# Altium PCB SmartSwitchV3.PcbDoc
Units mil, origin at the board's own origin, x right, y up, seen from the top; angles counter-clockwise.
Board outline 3850.26 x 3794.87 mil, 2 copper layers (Top Layer, Bottom Layer); 87 components, 65 nets, 326 pads, 45 vias.
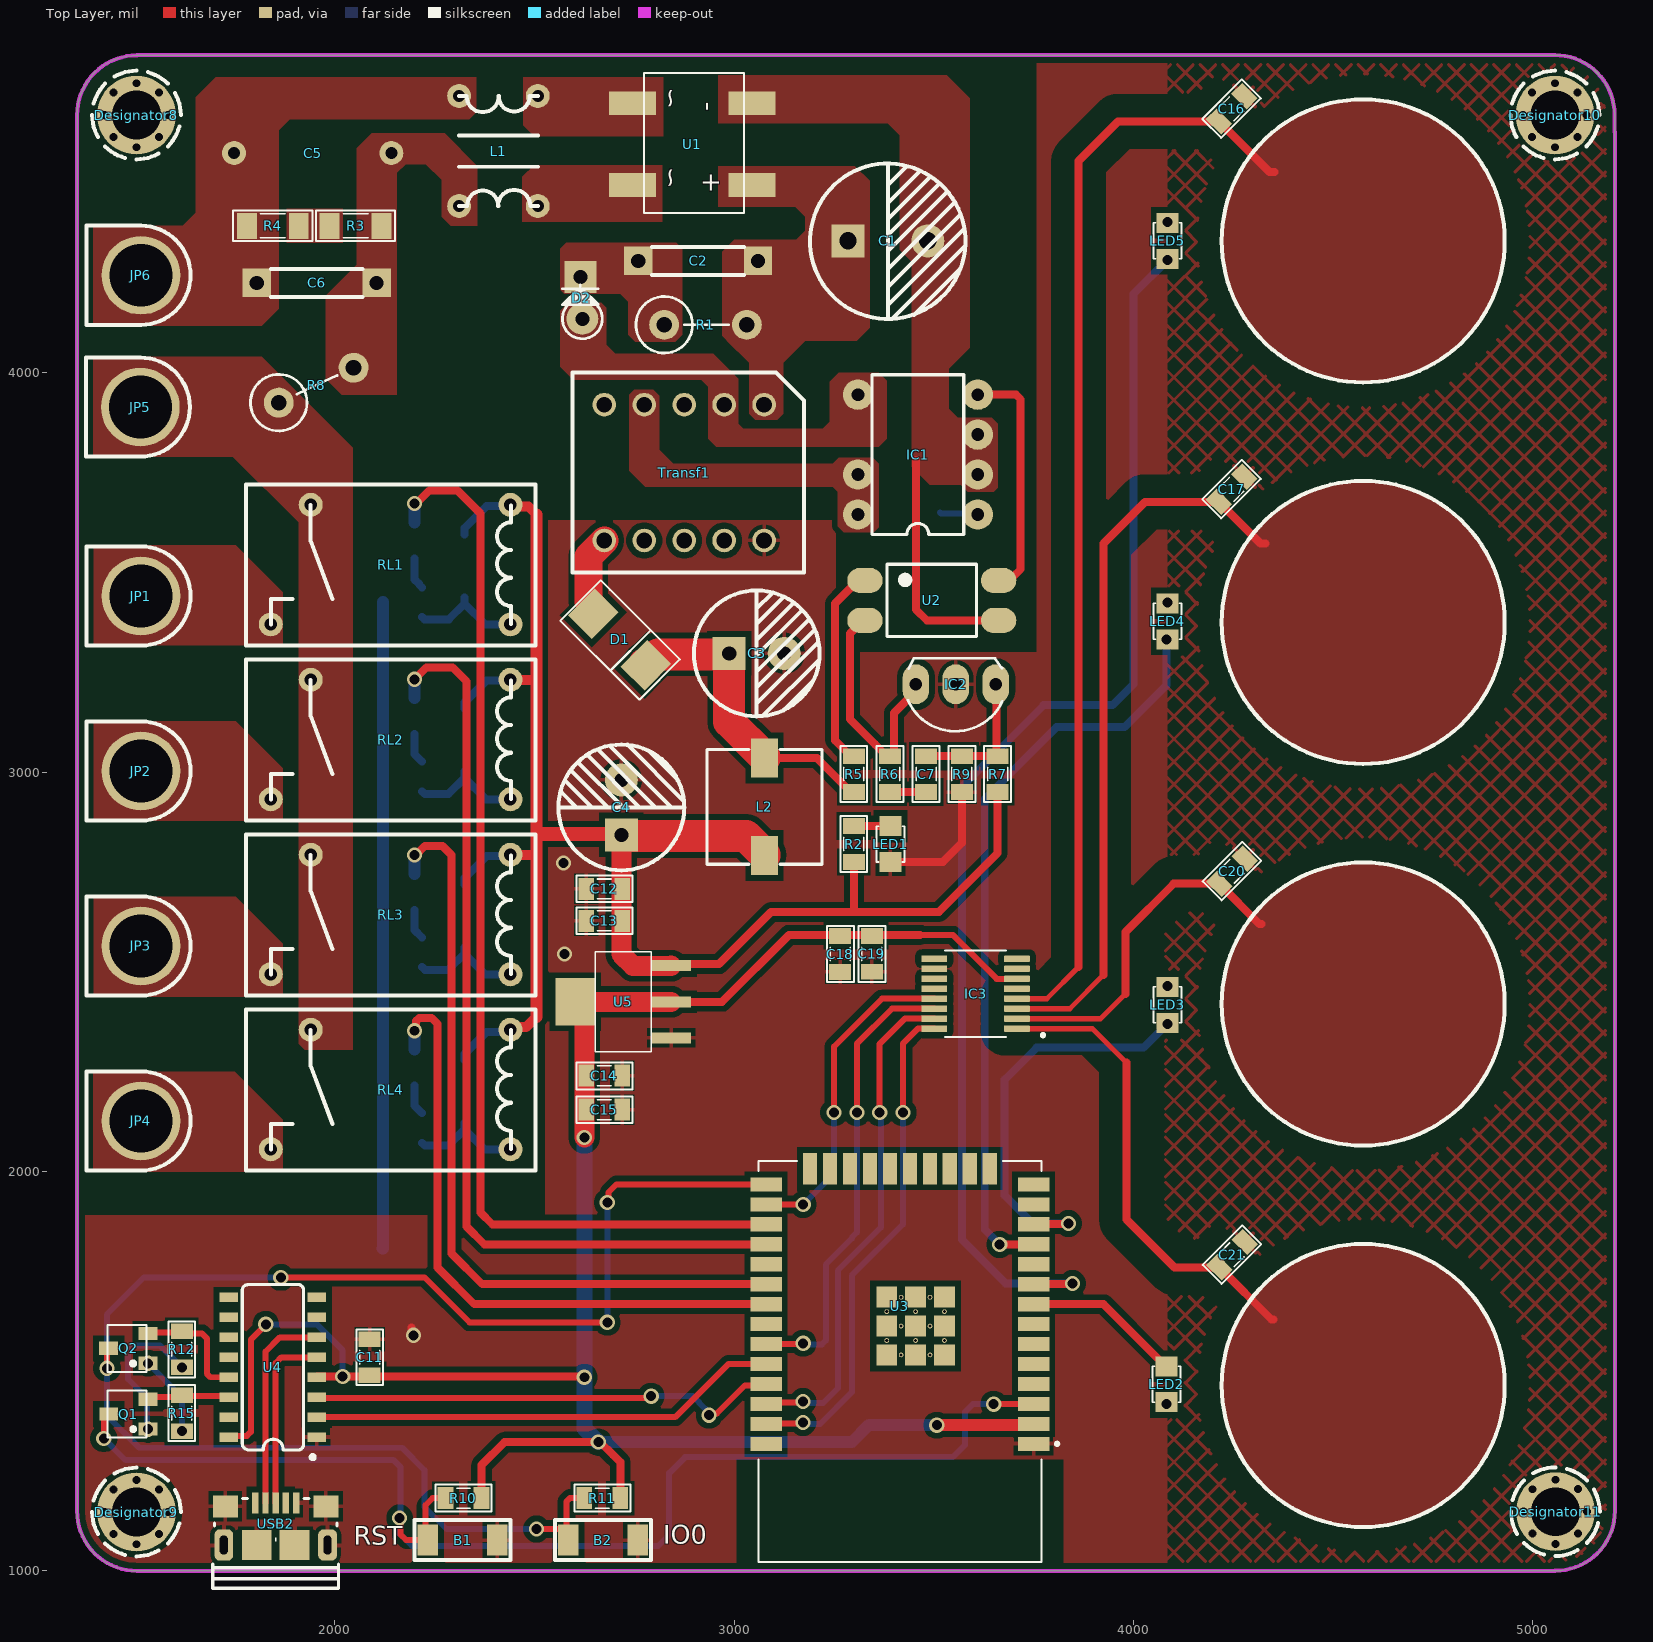
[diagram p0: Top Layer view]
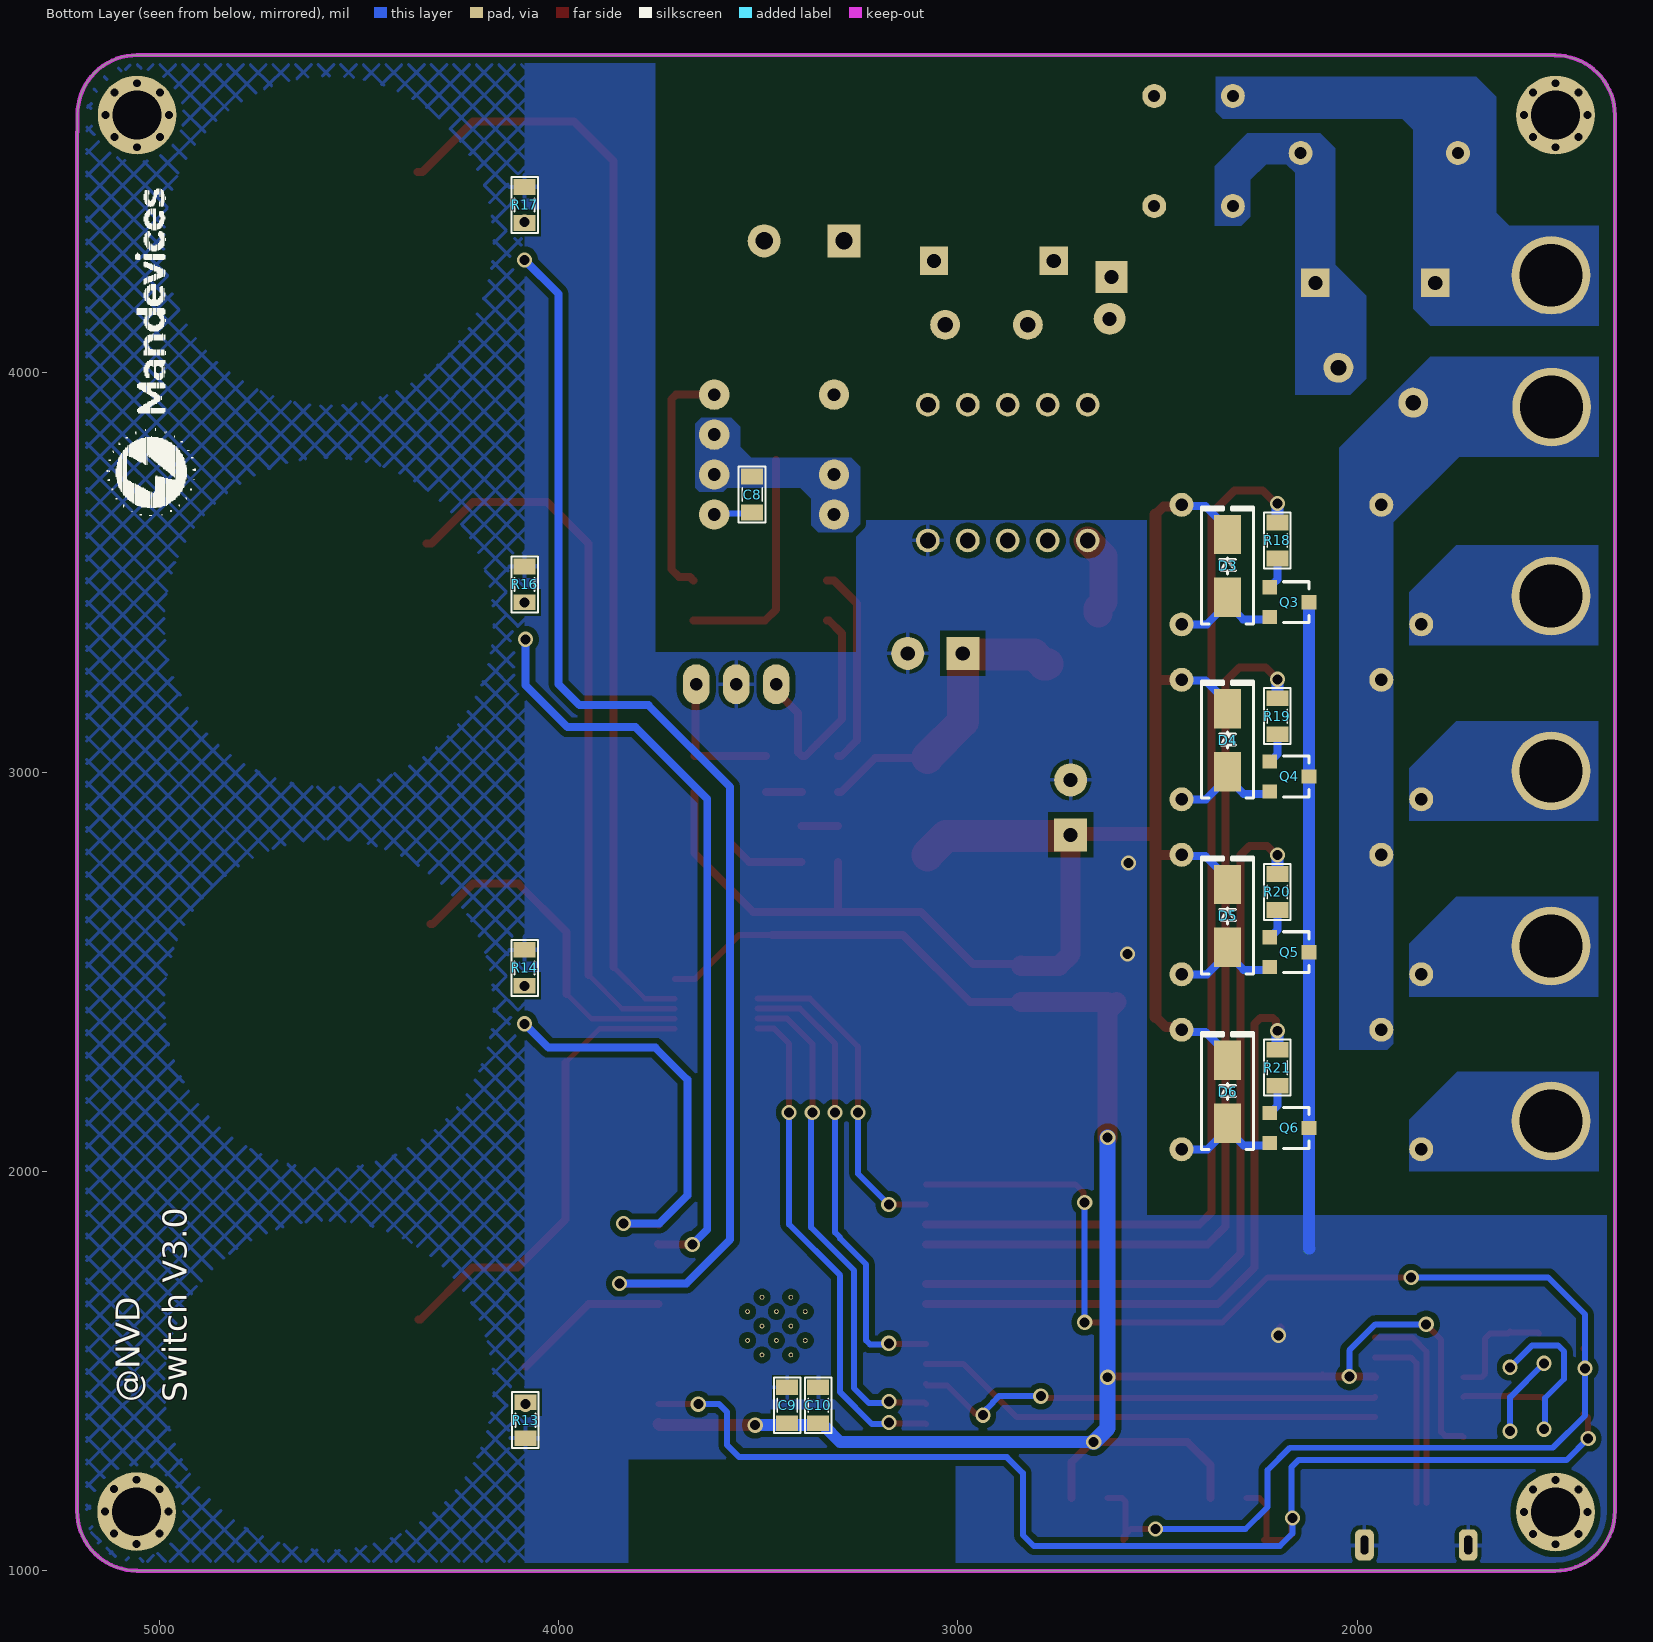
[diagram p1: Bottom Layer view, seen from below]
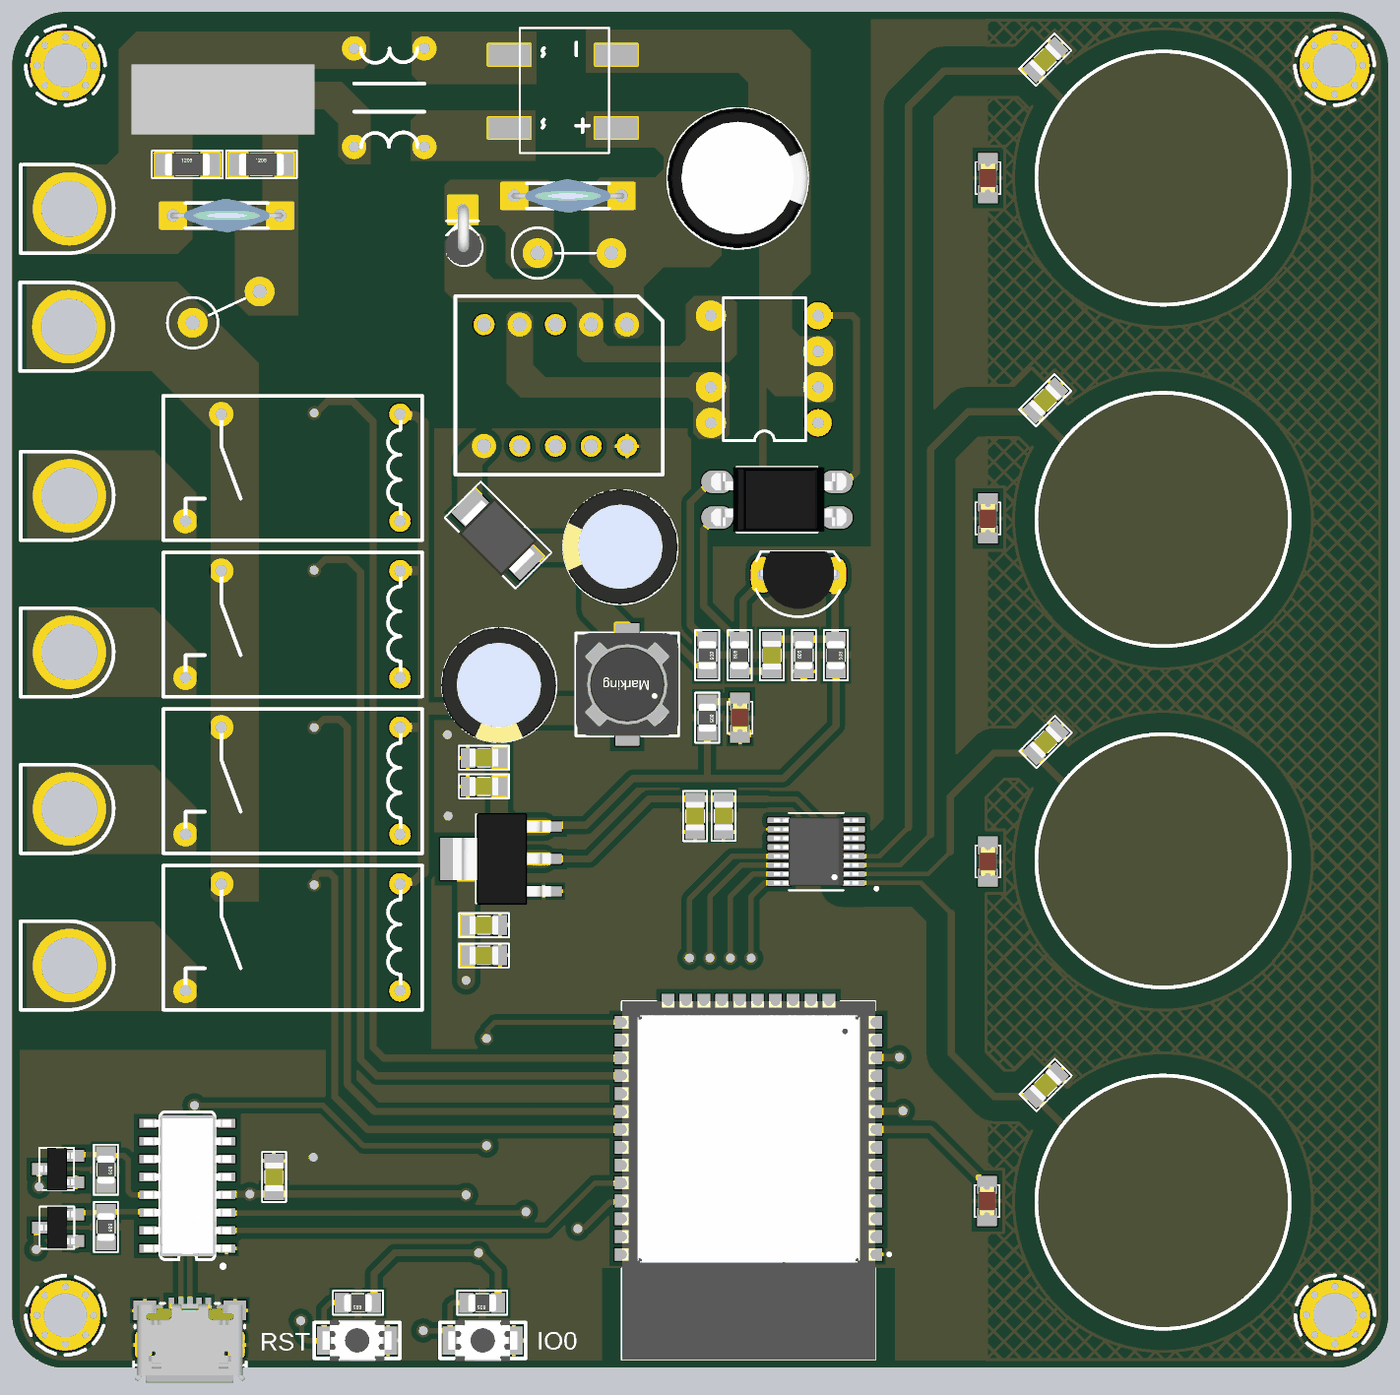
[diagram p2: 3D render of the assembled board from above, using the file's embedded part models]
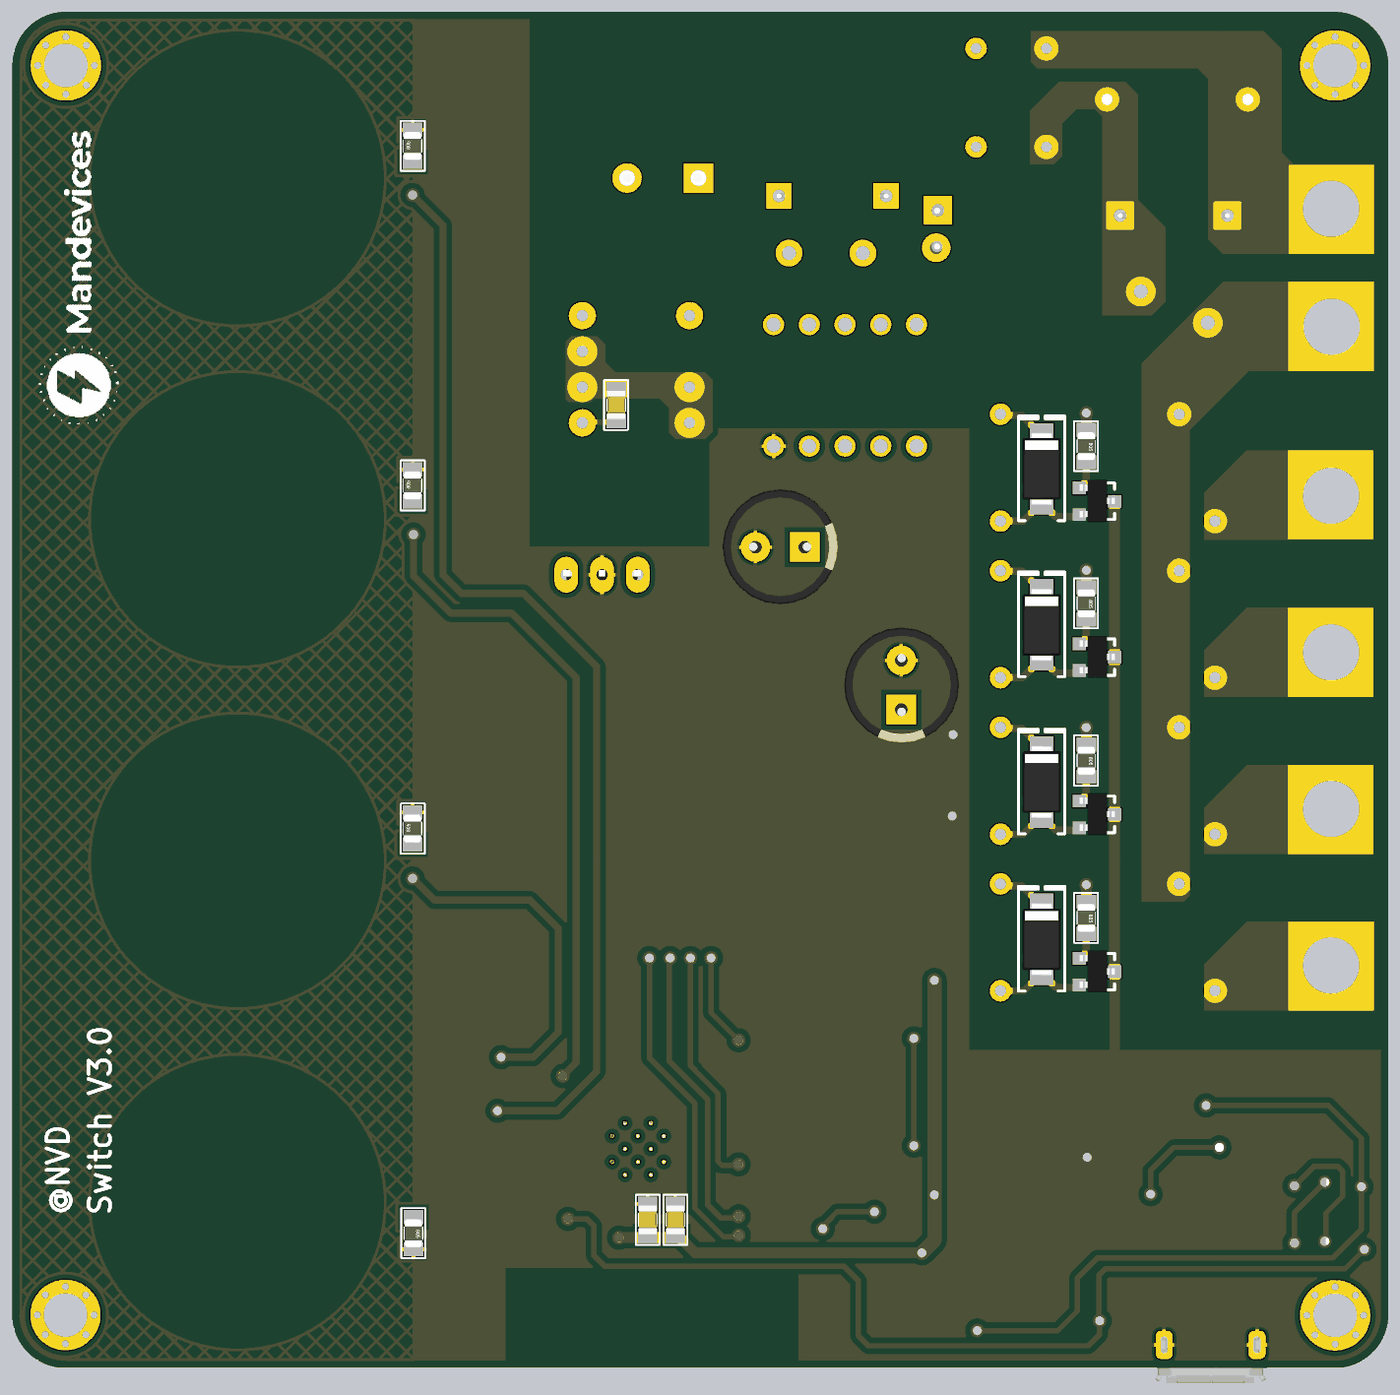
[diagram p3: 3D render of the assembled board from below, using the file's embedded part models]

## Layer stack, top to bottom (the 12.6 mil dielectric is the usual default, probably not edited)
Top Solder: solder mask 0.4, Solder Resist, Dk 3.5
Top Layer: signal copper 1.4
Dielectric 1: dielectric 12.6, FR-4, Dk 4.8
Bottom Layer: signal copper 1.4
Bottom Solder: solder mask 0.4, Solder Resist, Dk 3.5

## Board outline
1355,1150 ccw(c1504.61,1150) 1504.61,1000.39 5055.66,1000.39 ccw(c5055.55,1150.1) 5205.26,1150.21 5205,4602.5 5204.4,4602.5 5204.4,4645.66 ccw(c5054.79,4645.66) 5054.79,4795.26 1504.61,4795.26 1504.61,4794.61 ccw(c1504.61,4645) 1355,4645

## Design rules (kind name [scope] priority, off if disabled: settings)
Clearance Clearance_TP [InNetClass('TP')] p1: gap=59.06 ignorepadtopadclearanceinfootprint=TRUE
Clearance Clearance_AC [InNetClass('AC')] p2: gap=20 ignorepadtopadclearanceinfootprint=TRUE
Clearance Clearance_UART [InNet('D_N') vs InNet('D_P')] p3: gap=5 ignorepadtopadclearanceinfootprint=TRUE
Clearance [All] p4: gap=15 ignorepadtopadclearanceinfootprint=TRUE
PolygonConnect PolygonConnect_GND [InNet('GND')] p1: thpad.connectstyle=Relief thpad.reliefconductorwidth=10 thpad.reliefentries=4 thpad.polygonreliefangle="90 Angle" thpad.airgapwidth=10 smdpad.connectstyle=Relief smdpad.reliefconductorwidth=10 smdpad.reliefentries=4 smdpad.polygonreliefangle="90 Angle" smdpad.airgapwidth=10 via.connectstyle=Direct via.reliefconductorwidth=10 via.reliefentries=4 via.polygonreliefangle="90 Angle" via.airgapwidth=10
PolygonConnect PolygonConnect_AC [InNetClass('AC')] p2: connectstyle=Direct reliefconductorwidth=10 reliefentries=4 polygonreliefangle="90 Angle" airgapwidth=10
PolygonConnect [All] p3: connectstyle=Direct reliefconductorwidth=10 reliefentries=4 polygonreliefangle="90 Angle" airgapwidth=10
RoutingVias [All] p1: holewidth=25 width=38 viastyle="Through Hole" minholewidth=0 minwidth=30 maxholewidth=30 maxwidth=50
SolderMaskExpansion [All] p1: expansion=4 istentingtop=FALSE
Width [All] p1: maxlimit=100 minlimit=10 preferedwidth=20
30 further rules are at their usual default settings.

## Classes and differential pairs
net class TP: TP0 TP1 TP2 TP3
net class AC: L_1 L_2 L_3 L_4 L_AC NetC5_1

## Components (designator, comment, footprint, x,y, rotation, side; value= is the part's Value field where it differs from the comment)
B1 "Button 3x4x2.5" "Button 3x4x2.5" 2320,1077.5 r180 top
B2 "Button 3x4x2.5" "Button 3x4x2.5" 2671.61,1077.5 r180 top
C1 "10uF/400V" C10mm 3385.35,4332.44 r0 top
C2 "1nF/400V" 103/2KV 3060,4280 r180 top
C3 "680uF/16V" C8mm 3050,3300 r0 top
C4 "470uF/16V" C8mm 2715,2905 r90 top
C5 "0.1uF/275v" "Cap AC filter" 1945,4550 r0 top
C6 "14D471K" 103/2KV 1805,4225 r0 top
C7 "100nF" CAP_0805 3569.11,2997.15 r270 top value=33p
C8 "100nF" CAP_0805 3426.89,3697.15 r270 bottom value=33p
C9 "100nF" CAP_0805 3515.61,1412.85 r90 bottom value=33p
C10 "10uF" CAP_0805 3438.11,1412.85 r90 bottom value=33p
C11 "100nF" CAP_0805 1999.39,1532.85 r90 top value=33p
C12 "10uF" CAP_0805 2677.15,2619.39 r180 top value=33p
C13 "100nF" CAP_0805 2677.15,2539.39 r180 top value=33p
C14 "10uF" CAP_0805 2672.85,2328.11 r0 top value=33p
C15 "100nF" CAP_0805 2672.85,2243.11 r0 top value=33p
C16 "30pF" CAP_0805 4309.5,4599.9 r225 top value=33p
C17 "30pF" CAP_0805 4309.5,3647.4 r225 top value=33p
C18 "100nF" CAP_0805 3177.5,2542.5 r90 top value=33p
C19 "10uF" CAP_0805 3256.89,2542.85 r90 top value=33p
C20 "30pF" CAP_0805 4310.64,2691.03 r225 top value=33p
C21 "30pF" CAP_0805 4310.64,1731.03 r225 top value=33p
D1 "SS14" DO-214AA(SMB) 2707.5,3335 r135 top value=1N5007
D2 "1N4937" DIO-1AN 2615,4190 r270 top value=1N5007
D3 "M7" "DIODE SMA" 2325,3516.26 r90 bottom
D4 "M7" "DIODE SMA" 2325,3080 r90 bottom
D5 "M7" "DIODE SMA" 2325,2640 r90 bottom
D6 "M7" "DIODE SMA" 2325,2200 r90 bottom
Designator8 "Comment" HOLD 1503.73,4645 r0 top
Designator9 "Comment" HOLD 1503.73,1147.62 r0 top
Designator10 "Comment" HOLD 5055,4645 r0 top
Designator11 "Comment" HOLD 5056.23,1148.53 r0 top
IC1 "TNY264" TNY264 3656.85,3578.46 r90 top
IC2 "TL431" qto-92 3555,3220 r180 top
IC3 "TTP224" TTP224 3585,2425 r180 top
JP1 "Coc_dong" Coc_dong 1516.65,3436.93 r270 top
JP2 "Coc_dong" Coc_dong 1516.65,2998.86 r270 top
JP3 "Coc_dong" Coc_dong 1516.65,2560.79 r270 top
JP4 "Coc_dong" Coc_dong 1516.65,2122.72 r270 top
JP5 "Coc_dong" Coc_dong 1515,3910 r270 top
JP6 "Coc_dong" Coc_dong 1516.65,4240 r270 top
L1 "Inductor EE8.3" "Inductor EE8.3" 2410,4555 r90 top
L2 "22uH" L_SMD 3070,2925 r0 top value="150 mH"
LED1 "LED" LED-0805-Red 3391.5,2865 r270 top value="LED 3 ly Single Colour"
LED2 "LED" LED-0805-Red 4082.5,1512.5 r270 top value="LED 3 ly Single Colour"
LED3 "LED" LED-0805-Red 4085,2372.5 r90 top value="LED 3 ly Single Colour"
LED4 "LED" LED-0805-Red 4085,3332.5 r90 top value="LED 3 ly Single Colour"
LED5 "LED" LED-0805-Red 4085,4285 r90 top value="LED 3 ly Single Colour"
Q1 "C1815" SOT23D 1483.5,1393 r90 top
Q2 "C1815" SOT23D 1483.29,1557.4 r90 top
Q3 "2N2222" SOT23 2170,3425.44 r270 bottom value=C9014
Q4 "2N2222" SOT23 2170,2989.18 r270 bottom value=C9014
Q5 "2N2222" SOT23 2170,2549.18 r270 bottom value=C9014
Q6 "2N2222" SOT23 2170,2109.18 r270 bottom value=C9014
R1 "200k/2W" RES-1WW 2890,4120 r0 top
R2 "1k" RES-SMD-0805 3300,2820 r270 top
R3 "1M" RES-SMD-1206 2052.5,4367.5 r0 top
R4 "1M" RES-SMD-1206 1845,4367.5 r0 top
R5 "200R" RES-SMD-0805 3300,2995 r270 top
R6 "3.3k" RES-SMD-0805 3390,2995 r90 top
R7 "11k" RES-SMD-0805 3660,2995 r270 top
R8 "2R/2W" RES-1WW 1918.91,3952.47 r25 top
R9 "10k" RES-SMD-0805 3570,2995 r90 top
R10 "10k" RES-SMD-0805 2322.5,1182.5 r180 top
R11 "10k" RES-SMD-0805 2670,1182.5 r180 top
R12 "10k" RES-SMD-0805 1617.5,1555 r270 top
R13 "1k" RES-SMD-0805 4082.5,1377.5 r270 bottom
R14 "1k" RES-SMD-0805 4085,2510 r90 bottom
R15 "10k" RES-SMD-0805 1617.5,1395 r270 top
R16 "1k" RES-SMD-0805 4085,3470 r90 bottom
R17 "1k" RES-SMD-0805 4085,4420 r90 bottom
R18 "1k" RES-SMD-0805 2200,3580 r270 bottom
R19 "1k" RES-SMD-0805 2200,3140 r270 bottom
R20 "1k" RES-SMD-0805 2200,2700 r270 bottom
R21 "1k" RES-SMD-0805 2200,2260 r270 bottom
RL1 "Relay_HF32" HF32F 2504.17,3523.54 r180 top
RL2 "Relay_HF32" HF32F 2504.17,3085.47 r180 top
RL3 "Relay_HF32" HF32F 2504.17,2647.4 r180 top
RL4 "Relay_HF32" HF32F 2504.17,2209.33 r180 top
Transf1 "Transformer EE12.7" "Transformer EE12.7" 2875,3750 r180 top
U1 "Diode Bridge Flate" DB207S 2895,4570 r270 top
U2 "OPTO PC817 SMD" SOP4 3495,3430 r0 top value=PC817
U3 "ESP32-WROOM-32" MODULE_ESP32-WROOM-32 3415,1525 r180 top
U4 "CH340C" SO016 1845,1510 r90 top
U5 "LM1117-ADJ" LM1117-SOP 2792.5,2425 r90 top
USB2 "USB Micro 5p DIP" "USB Micro 5p DIP" 1852.24,1065 r0 top

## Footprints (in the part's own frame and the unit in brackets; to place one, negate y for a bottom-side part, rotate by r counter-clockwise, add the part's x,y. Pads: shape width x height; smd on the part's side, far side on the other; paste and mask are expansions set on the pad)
103/2KV [mm]
  rect 1.8x1.8 hole 0.9: 1(0,0) 2(7.62,0)
  silkscreen extent 0.89,-0.89 6.73,0.89, body extent -0.19,-1.2 7.81,1.19, height 9.03
"Button 3x4x2.5" [mm]
  rect 1.3x2 smd: 1(-2.2,0) 2(2.2,0)
  silkscreen extent -3.05,-1.27 3.05,1.27, body extent -2.45,-1.45 2.45,1.45, height 2
C8mm [mm]
  rect 2.1x2.1 hole 0.9: 1(-1.581,-0.069)
  round 2.1 hole 0.9: 2(1.919,-0.069)
  silkscreen extent -3.83,-4.07 4.17,3.93, body extent -3.93,-4.14 4.27,4.06, height 13.81
C10mm [mm]
  rect 2.1x2.1 hole 1.1: 1(-2.549,-0.062)
  round 2.1 hole 1.1: 2(2.531,-0.062)
  silkscreen extent -4.96,-5.02 4.92,4.85, body extent -5.01,-5.06 4.96,4.94, height 20.01
"Cap AC filter" [mil]
  round 60 hole 30: 1(-196.85,0) 2(196.85,0)
  body extent -256,-98 256,98, height 472
CAP_0805 [mil]
  rect 39.37x55 smd: 1(-42.85,-88.11) 2(47.15,-88.11)
  silkscreen extent -68,-122 72,-55, body extent -38,-114 42,-64, height 24
Coc_dong [mm]
  round 5 hole 4: 1(-0.1,-0.042)
  silkscreen extent -3.25,-3.5 3.05,3.11
DB207S [mm] "Bridge Rectifiers 2A 1000V"
  rect 1.5x3 smd: 1(2.54,3.81) 2(2.54,-3.785) 3(-2.667,-3.785) 4(-2.667,3.81)
  silkscreen extent -4.57,-3.05 4.32,3.3
DIO-1AN [mil] "Diode 1A, W 100mil, L 150mil"
  round 80 hole 35: 1(55,5)
  rect 80x80 hole 35: 2(-50,0)
  silkscreen extent -30,-45 105,55, body extent -64,-50 104,55, height 252
"DIODE SMA" [mm] "SMA"
  rect 2.5x1.7 smd: 1(-2,0) 2(2,0)
  silkscreen extent -3.68,-1.65 3.75,1.65, body extent -2.6,-1.37 2.6,1.37, height 2.4
DO-214AA(SMB) [mm] "DO-214AA Diode Middle Size"
  rect 2.16x2.4 smd: 1(2.184,-0.025) 2(-2.494,-0.076)
  silkscreen extent -3.76,-1.86 3.35,1.76, body extent -2.98,-1.76 2.42,1.86, height 2.43
HF32F [mm]
  round 1.524 hole 0.8: 1(16.87,3.9) 2(14.33,-3.7) 4(1.63,3.9) 5(1.63,-3.7)
  silkscreen extent 0.05,-5 18.45,5.25
HOLD [mm]
  round 0.5 hole 0.5: 2(-2.025,0) 2(-1.45,-1.4) 2(-1.45,1.425) 2(0,-2.05) 2(0,2.025) 2(1.429,-1.4) 2(1.429,1.434) 2(2,0)
  round 5 hole 3.1: 10(0,0)
  silkscreen extent -2.82,-2.82 2.82,2.82
"Inductor EE8.3" [mil]
  round 60 hole 30: 1(-137.8,-98.43) 2(-137.8,98.43) 3(137.8,-98.43) 4(137.8,98.43)
  silkscreen extent -138,-98 138,98
L_SMD [mm]
  rect 1.7x2.5 smd: 1(0.15,2.8) 2(0.15,-3.4)
  silkscreen extent -3.5,-3.95 3.8,3.35, body extent -3.5,-3.95 3.8,3.35, height 4.05
LED-0805-Red [mil]
  rect 50x55 smd: 1(0,0) 2(90,0)
  silkscreen extent 0,-35 90,35, body extent 5,-25 85,25, height 43
LM1117-SOP [mm]
  rect 0.7x2.54 smd: 1(-2.3,-1.27) 2(0,-1.27) 3(2.3,-1.27)
  rect 3x2.54 smd: 2(0,4.826)
  silkscreen extent -3.18,0 3.17,3.56, body extent -3.25,-1.78 3.25,5.18, height 1.68
MODULE_ESP32-WROOM-32 [mm]
  rect 2x0.9 smd: 1(-8.5,5.26) 2(-8.5,3.99) 3(-8.5,2.72) 4(-8.5,1.45) 5(-8.5,0.18) 6(-8.5,-1.09) 7(-8.5,-2.36) 8(-8.5,-3.63) 9(-8.5,-4.9) 10(-8.5,-6.17) 11(-8.5,-7.44) 12(-8.5,-8.71) 13(-8.5,-9.98) 14(-8.5,-11.25) 25(8.5,-11.25) 26(8.5,-9.98) 27(8.5,-8.71) 28(8.5,-7.44) 29(8.5,-6.17) 30(8.5,-4.9) 31(8.5,-3.63) 32(8.5,-2.36) 33(8.5,-1.09) 34(8.5,0.18) 35(8.5,1.45) 36(8.5,2.72) 37(8.5,3.99) 38(8.5,5.26)
  rect 0.9x2 smd: 15(-5.715,-12.25) 16(-4.445,-12.25) 17(-3.175,-12.25) 18(-1.905,-12.25) 19(-0.635,-12.25) 20(0.635,-12.25) 21(1.905,-12.25) 22(3.175,-12.25) 23(4.445,-12.25) 24(5.715,-12.25)
  rect 1.33x1.33 smd: 39_1(-2.835,-0.405) 39_2(-1,-0.405) 39_3(0.835,-0.405) 39_4(-2.835,-2.24) 39_5(-1,-2.24) 39_6(0.835,-2.24) 39_7(-2.835,-4.075) 39_8(-1,-4.075) 39_9(0.835,-4.075)
  round 0.3 hole 0.2: 39_10(-1.917,-0.405) 39_11(-0.082,-0.405) 39_12(-2.835,-1.322) 39_13(-1,-1.322) 39_14(0.835,-1.322) 39_15(-1.917,-2.24) 39_16(-0.082,-2.24) 39_17(-2.835,-3.157) 39_18(-1,-3.157) 39_19(0.835,-3.157) 39_20(-1.917,-4.075) 39_21(-0.082,-4.075)
  silkscreen extent -10.1,-12.75 9,12.75, body extent -9.02,-12.75 8.98,12.75, height 3.2
qto-92 [mil] "TO-92"
  oval 66x100 hole 32: 1(-100,0) 2(0,0) 3(100,0)
  silkscreen extent -117,-65 120,118, body extent -109,-66 109,95, height 245
RES-1WW [mm]
  round 1.905 hole 1: 1(-1.651,0) 2(3.6,0)
  silkscreen extent -3.45,-1.8 2.45,1.8
RES-SMD-0805 [mil]
  rect 39.37x55 smd: 1(-45,0) 2(45,0)
  silkscreen extent -70,-34 70,33, body extent -39,-25 39,25, height 31
RES-SMD-1206 [mil]
  rect 50x65 smd: 1(-65,0) 2(65,0)
  silkscreen extent -99,-38 99,39, body extent -63,-31 63,32, height 40
SO016 [mm]
  rect 0.6x1.2 smd: 1(-4.445,-2.8) 2(-3.175,-2.8) 3(-1.905,-2.8) 4(-0.635,-2.8) 5(0.635,-2.8) 6(1.905,-2.8) 7(3.175,-2.8) 8(4.445,-2.8) 9(4.445,2.8) 10(3.175,2.8) 11(1.905,2.8) 12(0.635,2.8) 13(-0.635,2.8) 14(-1.905,2.8) 15(-3.175,2.8) 16(-4.445,2.8)
  silkscreen extent -5.84,-2.67 5.26,1.95, body extent -4.99,-3.13 4.99,3.1, height 1.58
SOP4 [mm]
  oval 2.25x1.6 smd: 1(-4.25,1.27) 2(-4.25,-1.27) 3(4.25,-1.27) 4(4.25,1.27)
  silkscreen extent -2.85,-2.3 2.85,2.3, body extent -4.67,-2.29 4.93,2.31, height 3.6
SOT23 [mm] "SOT23"
  rect 0.9x0.95 smd: 1(-0.95,-1.25) 2(0,1.25)
  rect 0.9x0.95 smd mask+0: 3(0.95,-1.25)
  silkscreen extent -1.3,-0.38 1.3,1.25, body extent -1.52,-1.23 1.48,1.27, height 1.06
SOT23D [mm] "SOT 23C - 1-3-2 - BCE"
  rect 0.85x1.2 smd: 1(-0.95,-1.25) 2(0.94,-1.245) 3(0,1.25)
  silkscreen extent -1.5,-1.14 1.5,1.32, body extent -1.5,-1.17 1.5,1.33, height 1.06
TNY264 [mil] "Opto"
  round 76 hole 32: 1(66.54,46.85) 2(166.54,46.85) 3(266.54,46.85) 4(366.54,46.85) 5(366.54,346.85) 7(166.54,346.85) 8(66.54,346.85)
  silkscreen extent 17,82 417,312
"Transformer EE12.7" [mm]
  round 1.5 hole 1: 1(-5.08,-4.318) 2(-2.54,-4.318) 3(0,-4.318) 4(2.54,-4.318) 5(5.08,-4.318) 6(5.08,4.318) 7(2.54,4.318) 8(0,4.318) 9(-2.54,4.318) 10(-5.08,4.318)
  silkscreen extent -7.62,-6.35 7.11,6.35
TTP224 [mm]
  rrect25% 1.65x0.41 smd: 1(-3.129,1.71) 2(-3.129,1.075) 3(-3.129,0.44) 4(-3.129,-0.195) 5(-3.129,-0.829) 6(-3.129,-1.465) 7(-3.129,-2.1) 8(-3.129,-2.735) 9(2.131,-2.735) 10(2.131,-2.099) 11(2.131,-1.465) 12(2.131,-0.83) 13(2.131,-0.194) 14(2.131,0.44) 15(2.131,1.075) 16(2.131,1.71)
  silkscreen extent -4.88,-3.26 1.45,2.24, body extent -3.5,-2.96 2.5,1.94, height 1.75
"USB Micro 5p DIP" [mm]
  rect 0.4x1.35 smd mask+0.05: 1(-1.3,2.675) 2(-0.65,2.675) 3(0,2.675) 4(0.65,2.675) 5(1.3,2.675)
  rrect60% 1.2x2 hole 0.5 slot 1.2 at 90 deg: 5(-3.3,0) 5(3.3,0)
  rect 1.6x1.4 smd: 5(-3.2,2.45) 5(3.2,2.45)
  rect 1.9x1.9 smd paste-10: 5(-1.2,0) 5(1.2,0)
  silkscreen extent -4,-2.75 4,2.95, body extent -3.93,-2.76 3.93,2.9, height 2.85

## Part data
C1 C3 C4: library part "Cap Pol", "Polarized Capacitor (Axial)"
C2: library part Cap2KV, "CAP CERAMIC"
C5: library part "Cap AC filter", "Tụ lọc nguồn AC 0.1uf 275v 10mm"
C6: library part Cap2KV, "Capacitor Ceramic 2KV"
C7 C8 C9 C10 C11 C12 C13 C14 C15 C16 C17 C18 C19 C20 C21: library part CapSMD, "Capacitor"
D1: library part "Diode SMD", "Diode Schottky / 1N5819"
D2: library part "Diode SMD", "Diode Schottky / 1N4937"
D3 D4 D5 D6: library part "Diode M7 ( 4007 )", "Dán"
IC1: "IC Power"
IC2: "Programmable Shunt Regulator"
L2: library part Inductor, "CD73R 22uH 1.23A 7345"
LED1 LED2 LED3 LED4 LED5: "LED Single colour Green and Red"
Q1 Q2: library part 2SC1815, "NPN 600mW, ECB"
Q3 Q4 Q5 Q6: library part "C1815 HF SMD", "NPN transistor"
R1 R2 R3 R4 R5 R6 R7 R8 R9 R10 R11 R12 R13 R14 R15 R16 R17 R18 R19 R20 R21: library part "Resistor - SMD", "Resistor", Manufacturer="Generic Components"
Transf1: library part "Tranformer EE16"
U1: "Diode Bridge"
U2: "Single Opto"
U3: "Bluetooth, WiFi Transceiver Module 2.4GHz ~ 2.5GHz Surface Mount", Package="Module Espressif Systems"
U4: "USB to serial chip CH340", Package=Package
U5: "800mA Low-Dropout Linear Regulator"
USB2: "USB Type B"

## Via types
v1: diameter 38, hole 25, Top Layer to Bottom Layer, tented both sides, 45 vias

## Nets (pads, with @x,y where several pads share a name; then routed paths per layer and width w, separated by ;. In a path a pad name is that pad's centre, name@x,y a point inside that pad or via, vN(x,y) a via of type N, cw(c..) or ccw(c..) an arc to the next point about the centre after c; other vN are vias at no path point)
+3.3V: C9.1 C10.1 C11.1 C14.1 C15.1 C18.2 C19.2 IC3.6 R10.1 R11.1 U3.2 U4.4 U4.16 U5.2 | length 5290.9
  Top Layer w15: U4.16 1738.29,1338.53 1780.1,1338.53 1790,1348.43 1790,1579.22 1827.5,1616.72 v1(1827.5,1617.5) ; 3465,2592.5 3547.5,2592.5 3657.34,2482.66 IC3.6
  Top Layer w20: U4.4 1957.05,1486.81 v1(2020,1486.81) 2020.69,1487.5 2085,1487.5 C11.1 ; C11.1@2087.5,1487.5 2622.5,1487.5 v1(2625,1485) ; R10.1 2367.5,1265 2425,1322.5 2664.87,1322.5 2696.6,1290.77 2696.73,1290.77 2715,1272.5 R11.1 ; U5.2@2842.5,2425 2970,2425 3137.5,2592.5 3265.61,2592.5 3345,2592.5 3465,2592.5
  Top Layer w30: v1@3517.5,1365 3697.22,1365 3697.85,1365.63 3747.36,1365.63 U3.2
  Top Layer w50: U5.2@2602.5,2425 2625,2402.5 v1(2625,2085) ; U5.2@2625,2425 U5.2@2842.5,2425
  Bottom Layer w15: v1(1827.5,1617.5) 1955,1617.5 2020,1552.5 v1(2020,1486.81)
  Bottom Layer w30: v1(2660,1322.5) 3294.69,1322.5 3337.5,1365.31 C10.1@3350,1365.31 ; C10.1@3350,1365 3427.5,1365 v1(3507.5,1365)
  Bottom Layer w40: v1(2625,2085) 2625,1357.5 v1(2660,1322.5)
+5: C4.1 C12.1 C13.1 D3.2 D4.2 D5.2 D6.2 L2.2 R2.2 R7.2 RL1.5 RL2.5 RL3.5 RL4.5 U5.3 | length 4391.6
  Top Layer w20: U5.3 2846.28,2519.33 2961.83,2519.33 3092.5,2650 3302.5,2650 ; R2.2 3300,2652.5 3302.5,2650 ; R7.2 3660,2797.5 3512.5,2650 3302.5,2650
  Top Layer w25: RL4.5 2446.48,2361.48 2478.98,2361.48 2505,2387.5 ; RL3.5 2505,2793.07 ; RL2.5 2491.36,3231.14 ; RL1.5 2444.21,3665 2485,3665 2505,3645 ; 2505,2847.5 2507.25,2845.25
  Top Layer w30: 2505,2387.5 2505,2793.07 2505,2847.5 2505,3645 ; C4.1@2715.2,2845.25 C4.1
  Top Layer w35: 2507.25,2845.25 C4.1@2715.2,2845.25
  Top Layer w50: C4.1 2717.7,2544.29 2746.99,2515 2841.95,2515 U5.3
  Top Layer w80: C4.1 2719.04,2841.41 2745.15,2841.41 2746.55,2840 3029.72,2840 3075.91,2793.82 L2.2
  Bottom Layer w20: D6.2 2325,2294.49 2380,2349.49 2434.49,2349.49 RL4.5 ; D5.2 2325,2734.49 2380,2789.49 2436.42,2789.49 RL3.5 ; D4.2 2325,3174.49 2380,3229.49 2438.35,3229.49 RL2.5 ; D3.2 2325,3610.75 2380,3665.75 2436.54,3665.75 RL1.5
CH340_RXD: U3.35 U4.3 | length 1183.7
  Top Layer w15: U4.3 1956.74,1433.5 2788.5,1433.5 v1(2792.5,1437.5) ; v1(2937.5,1390) 2941.9,1394.4 2956.9,1394.4 3027.26,1464.76 3077.2,1464.76 U3.35
  Bottom Layer w15: v1(2792.5,1437.5) 2897.5,1437.5 2911.89,1423.11 2911.89,1421.84 2937.5,1396.22 v1(2937.5,1390)
CH340_TXD: U3.34 U4.2 | length 1180.2
  Top Layer w15: U4.2 2852.5,1385 2985.41,1517.91 U3.34
D_N: U4.6 USB2.2 | length 522.3
  Top Layer w15: USB2.2 1826.65,1549.15 1862.5,1585 U4.6
D_P: U4.5 USB2.3 | length 459.2
  Top Layer w15: USB2.3 1852.24,1520.59 1866.65,1535 U4.5
DTR: Q2.2 R12.1 U4.13 | length 293.5
  Top Layer w15: Q2.2@1544.79,1594.4 1547.59,1597.2 R12.1@1620.3,1597.2 ; R12.1 R12.1@1620.3,1597.2 ; U4.13 1688.79,1485 1680,1493.79 1680,1582.5 1667.5,1595 1622.5,1595 R12.1@1620.3,1597.2
EN: B1.2 Q1.3 R10.2 U3.3 | length 3158.3
  Top Layer w15: v1(1421.91,1331.91) 1421.91,1383.77 1431.14,1393 Q1.3 ; v1(2162.5,1132.5) 2165.22,1129.78 2165.22,1091 2178.72,1077.5 B1.2 2227.5,1083.39 2227.5,1165 2245,1182.5 R10.2 ; v1(3650,1417.5) 3650.21,1417.71 3749.44,1417.71 U3.3
  Bottom Layer w15: v1(1421.91,1331.91) 1476.31,1277.5 2147.5,1277.5 2165,1260 2165,1135 v1(2162.5,1132.5) 2162.5,1093.72 2193.72,1062.5 2810,1062.5 2837.5,1090 2837.5,1245 2877.5,1285 3547.5,1285 3577.5,1315 3577.5,1397.5 3597.5,1417.5 v1(3650,1417.5)
GND: B1.1 B2.1 C3.2 C4.2 C9.2 C10.2 C11.2 C12.2 C13.2 C14.2 C15.2 C16.1 C17.1 C18.1 C19.1 C20.1 C21.1 IC2.2 IC3.10 LED1.2 Q3.2 Q4.2 Q5.2 Q6.2 R9.1 R13.2 R14.2 R16.2 R17.2 Transf1.10 U3.1 U4.1 U5.1 USB2.5 | length 1968.9
  Top Layer w20: 2192.5,1610 2192.5,1590 v1(2197.5,1590) ; LED1.2 3522.5,2775 3570,2822.5 R9.1
  Bottom Layer w30: 2120,1807.5 2120.39,1807.89 2120.39,2108.78 Q6.2 Q5.2 Q4.2 Q3.2
  other v1: 2575,2545 2572.5,2772.5
GND_AC: C1.2 C8.1 IC1.2 IC1.3 IC1.7 IC1.8 Transf1.4 U1.4 U2.3 | length 592.1
  Top Layer w20: 3455,3780.91 3455,3407.5 3482.5,3380 U2.3
IO0: B2.2 Q2.3 R11.2 U3.25 | length 3856.1
  Top Layer w15: v1(1430,1507.5) 1430,1553.33 Q2.3 ; v1(1865,1735) 2225,1735 2337.5,1622.5 v1(2682.5,1622.5) ; v1(2505,1105) 2566.91,1105 B2.2@2580,1091.91 ; B2.2@2580,1082.5 B2.2@2580,1091.91 ; B2.2 2585,1086.91 B2.2@2580,1091.91 ; R11.2 2588.79,1182.5 2580,1173.71 B2.2@2580,1091.91 ; v1(2682.5,1922.5) 2685.59,1925.59 2685.59,1948.09 2705,1967.5 3079.94,1967.5 U3.25
  Bottom Layer w15: v1(1865,1735) 1522.5,1735 1430,1642.5 v1(1430,1507.5) 1430,1388.79 1510.29,1308.5 2169,1308.5 2225,1252.5 2225,1160 2280,1105 v1(2505,1105) ; v1(2682.5,1622.5) v1(2682.5,1922.5)
IO25: U3.10
IO26: LED4.1 U3.11 | length 1904.9
  Top Layer w20: v1(3665,1817.5) 3665.21,1817.71 3749.44,1817.71 U3.11 U3.11@3750.69,1818.96
  Bottom Layer w20: v1(3665,1817.5) 3627.5,1855 3627.5,2932.5 3807.5,3112.5 3977.5,3112.5 4082.5,3217.5 v1(4082.5,3332.5)
IO27: LED3.1 U3.12 | length 1033.2
  Top Layer w20: U3.12 3750.69,1868.96 3836.46,1868.96 v1(3837.5,1870)
  Bottom Layer w20: v1(3837.5,1870) 3747.5,1870 3677.5,1940 3677.5,2230 3757.5,2310 4025,2310 v1(4085,2370)
IO32: LED2.1 U3.8 | length 397.2
  Top Layer w20: U3.8 3924.59,1667.91 4080,1512.5 LED2.1
IO33: LED5.1 U3.9 | length 3188.7
  Top Layer w20: U3.9 3750.69,1718.96 3846.46,1718.96 v1(3847.5,1720)
  Bottom Layer w20: v1(3847.5,1720) 3680,1720 3570,1830 3570,2962.5 3775,3167.5 3947.5,3167.5 4000,3220 4000,4197.5 v1(4085,4282.5)
L_1: JP1.1 RL1.1
L_2: JP2.1 RL2.1
L_3: JP3.1 RL3.1
L_4: JP4.1 RL4.1
L_AC: JP5.1 R8.1 RL1.2 RL2.2 RL3.2 RL4.2
NetC1_1: C1.1 C2.1 R1.2 Transf1.1 U1.1
NetC2_2: C2.2 D2.2 R1.1
NetC3_1: C3.1 D1.2 L2.1 R5.2 | length 780.2
  Top Layer w20: L2.1 3206.95,3035.24 3292.19,2950 R5.2
  Top Layer w80: D1.2@2775.53,3271.22 D1.2@2776.42,3271.22 ; D1.2@2777.73,3269.91 2784.85,3269.91 2809.95,3295 2959.34,3295 2960.3,3295.96 2986.41,3295.96 C3.1 2987.75,3126.07 3075.91,3037.91 L2.1
NetC5_1: C5.1 C6.1 JP6.1 L1.4 R4.1
NetC5_2: C5.2 C6.2 L1.2 R3.2 R8.2
NetC7_1: C7.1 IC2.1 R7.1 R9.2 | length 361.1
  Top Layer w20: C7.1 R7.1 3657.5,3042.5 3657.5,3217.5 IC2.1
NetC7_2: C7.2 R6.1 | length 91
  Top Layer w20: R6.1 C7.2
NetC8_2: C8.2 IC1.1 | length 97.1
  Bottom Layer w15: C8.2 3517.5,3647.5 3607.5,3647.5 IC1.1
NetD1_1: D1.1 Transf1.6 | length 208
  Top Layer w70: D1.1 2650.74,3399.86 2650.74,3410.49 2635,3426.23 2635,3540 Transf1.6
NetD2_1: D2.1 IC1.5 Transf1.2
NetD3_1: D3.1 Q3.3 RL1.4 | length 276.5
  Bottom Layer w20: Q3.3 2224.75,3382.5 2285.73,3382.5 D3.1@2325,3421.77 ; D3.1 D3.1@2325,3421.77 ; RL1.4 2376.77,3370 D3.1@2325,3421.77
NetD4_1: D4.1 Q4.3 RL2.4 | length 278.3
  Bottom Layer w20: Q4.3 2225.99,2945 2284.49,2945 D4.1@2325,2985.51 ; D4.1 D4.1@2325,2985.51 ; RL2.4 2378.58,2931.93 D4.1@2325,2985.51
NetD5_1: D5.1 Q5.3 RL3.4 | length 277.5
  Bottom Layer w20: Q5.3 2225.99,2505 2284.49,2505 D5.1@2325,2545.51 ; D5.1 D5.1@2325,2545.51 ; RL3.4 2376.65,2493.86 D5.1@2325,2545.51
NetD6_1: D6.1 Q6.3 RL4.4 | length 276.7
  Bottom Layer w20: Q6.3 2225.99,2065 2284.49,2065 D6.1@2325,2105.51 ; D6.1 D6.1@2325,2105.51 ; RL4.4 2374.72,2055.79 D6.1@2325,2105.51
NetIC1_4: IC1.4 U2.4 | length 604.4
  Top Layer w20: IC1.4 3705.78,3945 3717.5,3933.28 3717.5,3508.02 3697.71,3488.23 3670.55,3488.23 U2.4
NetIC2_3: IC2.3 R6.2 U2.2 | length 611.3
  Top Layer w20: U2.2 3323.21,3380 3290,3346.79 3290,3132.54 3352.5,3070.04 3352.5,3069.69 3382.19,3040 3390.31,3040 3400,3049.69 3400,3148 3455,3203 IC2.3
NetL1_1: L1.1 U1.2
NetL1_3: L1.3 U1.3
NetLED1_1: LED1.1 R2.1 | length 91.5
  Top Layer w20: R2.1 LED1.1
NetLED2_2: LED2.2 R13.1 | length 5
  Top Layer w20: v1(4082.5,1417.5) LED2.2
NetLED3_2: LED3.2 R14.1 | length 0
  other v1: 4085,2465
NetLED4_2: LED4.2 R16.1 | length 0
  other v1: 4085,3425
NetLED5_2: LED5.2 R17.1 | length 2.5
  Bottom Layer w20: R17.1 v1(4085,4377.5)
NetQ1_1: Q1.1 R12.2 | length 380.4
  Top Layer w15: v1(1532.5,1355) 1532.5,1355.38 Q1.1
  Bottom Layer w15: v1(1532.5,1355) 1530,1357.5 1530,1433.11 1482.5,1480.61 1482.5,1550 1497.5,1565 1562.5,1565 v1(1617.5,1510)
NetQ2_1: Q2.1 R15.2 | length 205.2
  Bottom Layer w15: v1(1532.5,1520) 1617.5,1435 v1(1617.5,1350)
NetQ3_1: Q3.1 R18.2 | length 80.7
  Bottom Layer w20: R18.2 2200,3482.27 2210.51,3471.76 2210.51,3470.55 2218.23,3462.84 Q3.1
NetQ4_1: Q4.1 R19.2 | length 77
  Bottom Layer w20: R19.2 2200,3044.81 2218.23,3026.58 Q4.1
NetQ5_1: Q5.1 R20.2 | length 77
  Bottom Layer w20: R20.2 2200,2604.81 2218.23,2586.58 Q5.1
NetQ6_1: Q6.1 R21.2 | length 77
  Bottom Layer w20: R21.2 2200,2164.81 2218.23,2146.58 Q6.1
NetR3_1: R3.1 R4.2
NetR5_1: R5.1 U2.1 | length 505.7
  Top Layer w20: R5.1 3292.19,3040 3252.5,3079.69 3252.5,3422.5 3310,3480 U2.1
RL1: R18.1 U3.27 | length 2727.4
  Top Layer w20: v1(2200,3672.5) 2204.3,3672.5 2236.8,3705 2307.5,3705 2365,3647.5 2365,1897.5 2394.59,1867.91 U3.27
  Bottom Layer w30: R18.1 v1(2200,3672.5)
RL2: R19.1 U3.28 | length 2338.2
  Top Layer w20: v1(2200,3232.5) 2230,3262.5 2295,3262.5 2330,3227.5 2330,1862.5 2374.59,1817.91 U3.28
  Bottom Layer w30: R19.1 v1(2200,3232.5)
RL3: R20.1 U3.30 | length 1975.9
  Top Layer w20: v1(2200,2792.5) 2203.22,2792.5 2225.72,2815 2270,2815 2292.5,2792.5 2292.5,1795 2369.59,1717.91 U3.30
  Bottom Layer w30: R20.1 v1(2200,2792.5)
RL4: R21.1 U3.31 | length 1607.8
  Top Layer w20: v1(2200,2352.5) 2203.44,2355.94 2203.44,2376.73 2211.72,2385 2242.5,2385 2257.5,2370 2257.5,1760 2349.59,1667.91 U3.31
  Bottom Layer w30: R21.1 v1(2200,2352.5)
RST: Q1.2 R15.1 U4.14 | length 208.5
  Top Layer w15: Q1.2 1537.5,1435 1612.5,1435 R15.1 1620,1437.5 1732.26,1437.5 U4.14
TP0: C21.2 IC3.1 | length 1173.1
  Top Layer w13: IC3.1 3897.34,2357.66 3982.5,2272.5
  Top Layer w20: 3982.5,2272.5 3982.5,1880 4102.5,1760 C21.2 4345,1630 4350,1630
TP1: C20.2 IC3.2 | length 884.3
  Top Layer w13: IC3.2 3917.66,2382.66 3980,2445
  Top Layer w20: 3980,2445 3980,2600 4100.65,2720.65 4214.35,2720.65 C20.2 4315,2620 4320,2620
TP2: C17.2 IC3.3 | length 1823
  Top Layer w13: IC3.3 3840.16,2407.66 3925,2492.5
  Top Layer w20: 3925,2492.5 3925,3572.5 4028.86,3676.36 C17.2 4317.72,3572.5 4330,3572.5
TP3: C16.2 IC3.4 | length 2788.2
  Top Layer w13: IC3.4 3782.66,2432.66 3862.5,2512.5
  Top Layer w20: 3862.5,2512.5 3862.5,4530 3961.36,4628.86 C16.2 4340.22,4502.5 4352.5,4502.5
TPQ0: IC3.16 U3.37 | length 1270.4
  Top Layer w15: U3.37 3082.15,1369.71 3170.71,1369.71 v1(3172.5,1371.5) ; v1(3422.5,2147.5) 3422.5,2320 3460.04,2357.54 3500.98,2357.54 IC3.16
  Bottom Layer w15: v1(3172.5,1371.5) 3176.5,1367.5 3215,1367.5 3295,1447.5 3295,1740 3422.5,1867.5 v1(3422.5,2147.5)
TPQ1: IC3.15 U3.36 | length 1269.9
  Top Layer w15: U3.36 3083.65,1421.21 3169.21,1421.21 v1(3172.5,1424.5) ; v1(3364.5,2147.5) 3364.5,2319.5 3427.66,2382.66 IC3.15
  Bottom Layer w15: v1(3172.5,1424.5) 3176.5,1420.5 3223,1420.5 3260,1457.5 3260,1752.5 3367.5,1860 3367.5,2144.5 v1(3364.5,2147.5)
TPQ2: IC3.14 U3.33 | length 1158.5
  Top Layer w15: U3.33 3080.56,1567.71 3172.79,1567.71 v1@3173,1567.5 ; v1(3307.5,2147.5) 3307.5,2320 3395.16,2407.66 IC3.14
  Bottom Layer w15: v1@3173,1567.5 3220,1567.5 3230,1577.5 3230,1767.5 3295,1832.5 3295,1835 3307.5,1847.5 v1(3307.5,2147.5)
  other v1: 3173,1570
TPQ3: IC3.13 U3.26 | length 820.6
  Top Layer w15: U3.26 3080.56,1917.71 3172.79,1917.71 v1(3173,1917.5) ; v1(3250,2147.5) 3250,2312.5 3370.16,2432.66 IC3.13
  Bottom Layer w15: v1(3173,1917.5) 3250,1994.5 v1(3250,2147.5)
pads on no net: Designator8.2 Designator8.10 Designator9.2 Designator9.10 Designator10.2 Designator10.10 Designator11.2 Designator11.10 IC3.5 IC3.7 IC3.8 IC3.9 IC3.11 IC3.12 Transf1.3 Transf1.5 Transf1.7 Transf1.8 Transf1.9 U3.4 U3.5 U3.6 U3.7 U3.13 U3.14 U3.15 U3.16 U3.17 U3.18 U3.19 U3.20 U3.21 U3.22 U3.23 U3.24 U3.29 U3.32 U3.38 U3.39_1 U3.39_2 U3.39_3 U3.39_4 U3.39_5 U3.39_6 U3.39_7 U3.39_8 U3.39_9 U3.39_10 U3.39_11 U3.39_12 U3.39_13 U3.39_14 U3.39_15 U3.39_16 U3.39_17 U3.39_18 U3.39_19 U3.39_20 U3.39_21 U4.7 U4.8 U4.9 U4.10 U4.11 U4.12 U4.15 USB2.1 USB2.4

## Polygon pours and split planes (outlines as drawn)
GND on Top Layer "100" (hatched 45Degree grid 40 track 8, pour order 47): 4079.99,1000 4079.99,4795 cw(c4085,4795) 4085,4800.02 5054.54,4800.02 cw(c5054.78,4644.76) 5210.04,4645 5210.04,1144.95 cw(c5061.05,1144.95) 5061.05,995.96 4087.97,995.96 cw(c4085,1000)
GND on Top Layer "100" (solid, pour order 43): 3757.5,4795 4085,4795 4085,1000 1355,1000 1355,1890 2527.5,1890 2527.5,3630 3255,3630 3255,3300 3757.5,3300
L_AC on Top Layer "100" (solid, pour order 36): 1395,3790 1395,4040 1817.5,4040 2045,3812.5 2045,2305 1925,2305 1910,2320 1910,3625 1745,3790
L_4 on Top Layer "100" (solid, pour order 6): 1750,2250 1870,2130 1870,1999.72 1395,1999.72 1395,2250
L_3 on Top Layer "100" (solid, pour order 7): 1751.82,2687.91 1870,2569.73 1870,2437.91 1396.82,2437.91 1396.82,2687.91
L_2 on Top Layer "100" (solid, pour order 8): 1751.82,3127.91 1870,3009.73 1870,2877.91 1396.82,2877.91 1396.82,3127.91
L_1 on Top Layer "100" (solid, pour order 9): 1751.82,3567.91 1870,3449.73 1870,3317.91 1396.82,3317.91 1396.82,3567.91
NetC5_2 on Top Layer "100" (solid, pour order 35): 1965,3997.5 2017.5,3945 2155,3945 2155,4500 2177.5,4522.5 2227.5,4522.5 2267.5,4482.5 2267.5,4390 2290,4367.5 2357.5,4367.5 2357.5,4517.5 2275,4600 2092.5,4600 2055,4562.5 2055,4270 1977.5,4192.5 1977.5,3985
NetC5_1 on Top Layer "100" (solid, pour order 33): 1652.5,4572.5 1652.5,4690 1702.5,4740 2355,4740 2355,4652.5 2337.5,4635 1887.5,4635 1860,4607.5 1860,4562.5 1652.5,4562.5
NetC5_1 on Top Layer "100" (solid, pour order 30): 1395,4117.5 1817.5,4117.5 1860,4160 1860,4572.5 1652.5,4572.5 1652.5,4400 1620,4367.5 1395,4367.5
GND_AC on Top Layer "100" (solid, pour order 26): 3590,4277.5 3590,4062.5 3537.5,4010 3537.5,3910 3560,3887.5 3645,3887.5 3660,3872.5 3660,3712.5 3650,3702.5 3585,3702.5 3567.5,3720 3490,3720 3445,3765 3445,4277.5
GND_AC on Top Layer "100" (solid, pour order 23): 3347.5,3787.5 3262.5,3787.5 3247.5,3772.5 2847.5,3772.5 2812.5,3807.5 2812.5,3942.5 2797.5,3957.5 2750,3957.5 2737.5,3945 2737.5,3755 2777.5,3715 3247.5,3715 3260,3702.5 3260,3615 3275,3600 3350,3600 3362.5,3612.5 3362.5,3772.5
NetD2_1 on Top Layer "100" (solid, pour order 21): 3010,3900 3010,3872.5 3022.5,3860 3222.5,3860 3240,3877.5 3240,3977.5 3262.5,4000 3362.5,4000 3382.5,3980 3382.5,3835 3362.5,3815 2955,3815 2935,3835 2935,3900
NetD2_1 on Top Layer "100" (solid, pour order 20): 2565,4155 2585,4175 2667.5,4175 2680,4162.5 2680,4070 2702.5,4047.5 2947.5,4047.5 3010,3985 3010,3890 2997.5,3877.5 2957.5,3877.5 2935,3900 2935,3965 2917.5,3982.5 2597.5,3982.5 2565,4015
NetC1_1 on Top Layer "100" (solid, pour order 19): 2977.5,4085 3037.5,4025 3037.5,3897.5 3052.5,3882.5 3107.5,3882.5 3122.5,3897.5 3122.5,4025 3182.5,4085
NetC2_2 on Top Layer "100" (solid, pour order 18): 2565,4310 2580,4325 2855,4325 2870,4310 2870,4095 2852.5,4077.5 2752.5,4077.5 2735,4095 2735,4177.5 2715,4197.5 2575,4197.5 2565,4207.5
NetC1_1 on Top Layer "100" (solid, pour order 17): 2960,4517.5 3302.5,4517.5 3340,4480 3340,4112.5 3307.5,4080 2982.5,4080 2970,4092.5 2970,4302.5 3000,4332.5 3155,4332.5 3177.5,4355 3177.5,4390 3152.5,4415 2960,4415
GND_AC on Top Layer "100" (solid, pour order 16): 2960,4745 3532.5,4745 3590,4687.5 3590,4267.5 3455,4267.5 3415,4307.5 3415,4595 3385,4625 2960,4625
NetL1_1 on Top Layer "100" (solid, pour order 13): 2470,4490 2500,4520 2820,4520 2820,4377.5 2470,4377.5
NetL1_3 on Top Layer "100" (solid, pour order 12): 2472.5,4740 2822.5,4740 2822.5,4592.5 2500,4592.5 2472.5,4620
NetR3_1 on Top Layer "100" (solid, pour order 11): 1880,4410 2020,4410 2020,4325 1880,4325
TP0 on Top Layer "100" (solid, pour order 5): 4220.67,1464.3 ccw(c4575,1464.3) 4575,1109.97 ccw(c4575,1464.3) 4929.33,1464.3 ccw(c4575,1464.3) 4575,1818.63 ccw(c4575,1464.3)
TP1 on Top Layer "100" (solid, pour order 4): 4220.67,2419.53 ccw(c4575,2419.53) 4575,2065.2 ccw(c4575,2419.53) 4929.33,2419.53 ccw(c4575,2419.53) 4575,2773.86 ccw(c4575,2419.53)
TP3 on Top Layer "100" (solid, pour order 1): 4220.67,4330 ccw(c4575,4330) 4575,3975.67 ccw(c4575,4330) 4929.33,4330 ccw(c4575,4330) 4575,4684.33 ccw(c4575,4330)
TP2 on Top Layer "100" (solid, pour order 3): 4220.67,3374.77 ccw(c4575,3374.77) 4575,3020.44 ccw(c4575,3374.77) 4929.33,3374.77 ccw(c4575,3374.77) 4575,3729.1 ccw(c4575,3374.77)
GND on Bottom Layer "100" (hatched 45Degree grid 40 track 8, pour order 48): 4080.28,1005 4080.28,4800 cw(c4085.3,4800) 4085.3,4805.01 5054.84,4805.01 cw(c5055.08,4649.76) 5210.34,4650 5210.34,1149.95 cw(c5061.35,1149.95) 5061.35,1000.96 4088.27,1000.96 cw(c4085.3,1005)
GND on Bottom Layer "100" (solid, pour order 44): 3757.5,4795 4085,4795 4085,1000 1355,1000 1355,1890 2527.5,1890 2527.5,3630 3255,3630 3255,3300 3757.5,3300
L_4 on Bottom Layer "100" (solid, pour order 42): 1750,2250 1870,2130 1870,2000.78 1395,2000.78 1395,2250
L_3 on Bottom Layer "100" (solid, pour order 41): 1751.82,2687.91 1870,2569.73 1870,2437.91 1396.82,2437.91 1396.82,2687.91
L_2 on Bottom Layer "100" (solid, pour order 40): 1751.82,3127.91 1870,3009.73 1870,2877.91 1396.82,2877.91 1396.82,3127.91
L_1 on Bottom Layer "100" (solid, pour order 39): 1751.82,3567.91 1870,3449.73 1870,3317.91 1396.82,3317.91 1396.82,3567.91
L_AC on Bottom Layer "100" (solid, pour order 38): 1395.39,3790.15 1395.39,4040.15 1817.89,4040.15 2045.39,3812.65 2045.39,2305.15 1925.39,2305.15 1910,2320.54 1910,3625.54 1745.39,3790.15
NetC5_2 on Bottom Layer "100" (solid, pour order 37): 1965,3997.5 2017.5,3945 2155,3945 2155,4500 2177.5,4522.5 2227.5,4522.5 2267.5,4482.5 2267.5,4390 2290,4367.5 2357.5,4367.5 2357.5,4517.5 2275,4600 2092.5,4600 2055,4562.5 2055,4270 1977.5,4192.5 1977.5,3985
NetC5_1 on Bottom Layer "100" (solid, pour order 34): 1652.5,4573.75 1652.5,4691.25 1702.5,4741.25 2355,4741.25 2355,4653.75 2337.5,4636.25 1887.5,4636.25 1860,4608.75 1860,4563.75 1652.5,4563.75
NetC5_1 on Bottom Layer "100" (solid, pour order 32): 1395,4117.5 1817.5,4117.5 1860,4160 1860,4572.5 1652.5,4572.5 1652.5,4400 1620,4367.5 1395,4367.5
GND_AC on Bottom Layer "100" (solid, pour order 25): 3657.5,3872.5 3642.5,3887.5 3567.5,3887.5 3545,3865 3545,3815 3517.5,3787.5 3267.5,3787.5 3245,3765 3245,3620 3265,3600 3350,3600 3367.5,3617.5 3367.5,3685 3395,3712.5 3577.5,3712.5 3587.5,3702.5 3647.5,3702.5 3657.5,3712.5
L_4 on Bottom Solder "100" (solid): 1394.69,2250.62 1634.32,2250.62 1634.32,2000.62 1394.69,2000.62
L_3 on Bottom Solder "100" (solid): 1396.49,2688.25 1636.11,2688.25 1636.11,2438.25 1396.49,2438.25
L_2 on Bottom Solder "100" (solid): 1396.75,3127.45 1636.38,3127.45 1636.38,2877.45 1396.75,2877.45
L_1 on Bottom Solder "100" (solid): 1396.06,3568.05 1635.69,3568.05 1635.69,3318.05 1396.06,3318.05
NetC5_1 on Bottom Solder "100" (solid): 1394.39,4367.35 1634.01,4367.35 1634.01,4117.35 1394.39,4117.35
L_AC on Bottom Solder "100" (solid, pour order 49): 1395,4040 1634.63,4040 1634.63,3790 1395,3790

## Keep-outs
Keep-Out Layer:
  lines w10: 1504.61,4794.61 ccw(c1504.61,4645) 1355,4645 1355,1947.5 1355,1150 ccw(c1504.61,1150) 1504.61,1000.39 4930,1000.39 5055.66,1000.39 ; 1504.61,4795.26 5054.79,4795.26 cw(c5054.79,4645.66) 5204.4,4645.66 5204.4,4602.5 5205,4602.5 5205,1150.21 5205.26,1150.21 cw(c5055.66,1150.21) 5055.66,1000.6

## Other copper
Bottom Layer:
  pour cut-out: 4161.61,1464.3 ccw(c4575,1464.3) 4575,1050.91 ccw(c4575,1464.3) 4988.39,1464.3 ccw(c4575,1464.3) 4575,1877.69 ccw(c4575,1464.3)
  pour cut-out: 4161.61,2419.53 ccw(c4575,2419.53) 4575,2006.15 ccw(c4575,2419.53) 4988.39,2419.53 ccw(c4575,2419.53) 4575,2832.92 ccw(c4575,2419.53)
  pour cut-out: 4161.61,3374.77 ccw(c4575,3374.77) 4575,2961.38 ccw(c4575,3374.77) 4988.39,3374.77 ccw(c4575,3374.77) 4575,3788.15 ccw(c4575,3374.77)
  pour cut-out: 4161.61,4330 ccw(c4575,4330) 4575,3916.61 ccw(c4575,4330) 4988.39,4330 ccw(c4575,4330) 4575,4743.39 ccw(c4575,4330)
Multi-Layer:
  pour cut-out: 3005,992.5 3005,1280 3825,1280 3825,992.5

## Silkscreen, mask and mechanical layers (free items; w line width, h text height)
Top Overlay:
  circle w10: c4575,2419.53 r354.33
  circle w10: c4575,3374.77 r354.33
  circle w10: c4575,1464.3 r354.33
  circle w10: c4575,4330 r354.33
  text "IO0" at 2822.56,1052.3 h80
  text "RST" at 2047.63,1049.68 h80
Bottom Overlay:
  drawing of 653 lines, arcs and shapes, not listed
  text "Switch V3.0" at 4931.19,1422.52 h60 r270
  text "@NVD" at 5048.69,1422.52 h60 r270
